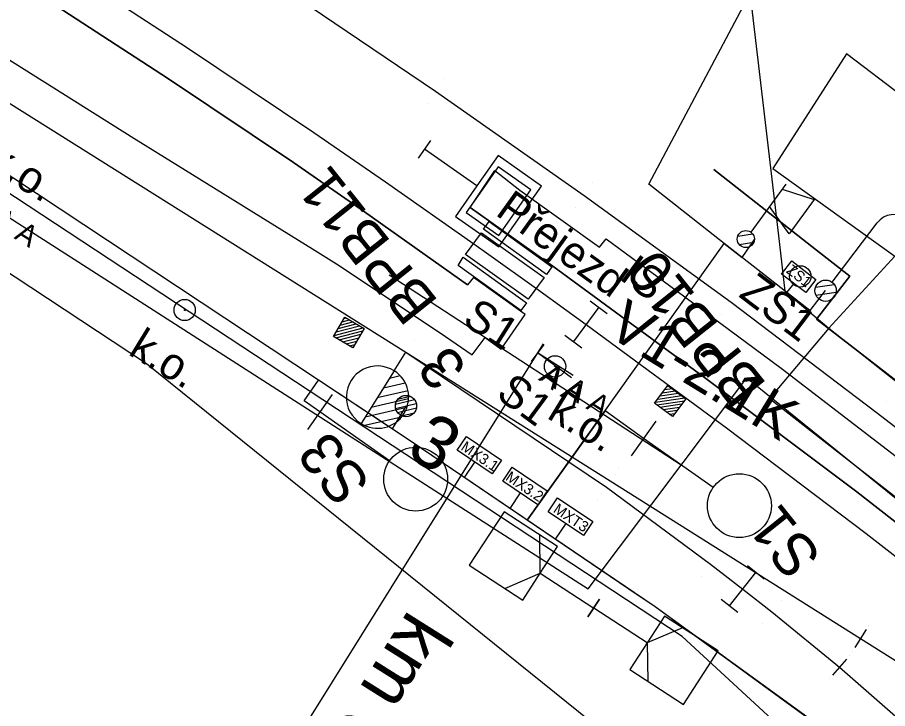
# Model space of a CAD drawing. Extents: x -620475 to -619963, y -1123010 to -1122510.
# Drawn here: x -620340.78 to -620299.89, y -1122684.84 to -1122652.35 of the extents above; entities that cross this region are included whole.
import ezdxf

# ---------------------------------------------------------------- set-up
doc = ezdxf.new("R2010")
doc.units = 0
for name, color, linetype in [('060601_EOV', 7, 'Continuous'), ('060604_ROZVODY_SEE', 7, 'Continuous'), ('HranDP', 7, 'Continuous'), ('Hranice parcel', 7, 'Continuous'), ('lomové body trasa', 7, 'Continuous'), ('PS 06-14-01_trasa_sdělovací_nové', 7, 'Continuous'), ('SEE', 7, 'Continuous'), ('SSZT', 7, 'Continuous'), ('UZEMNĚNÍ', 7, 'Continuous'), ('Vrstva 1', 7, 'Continuous'), ('Vrstva 12', 7, 'Continuous'), ('Vrstva 14', 7, 'Continuous'), ('Vrstva 16', 7, 'Continuous'), ('Vrstva 2', 7, 'Continuous'), ('Vrstva 25', 7, 'Continuous'), ('Vrstva 27', 7, 'Continuous'), ('Vrstva 3', 7, 'Continuous'), ('Vrstva 33', 7, 'Continuous'), ('Vrstva 4', 7, 'Continuous'), ('Vrstva 51', 7, 'Continuous'), ('Vrstva 6', 7, 'Continuous'), ('Vrstva 62', 7, 'Continuous'), ('Vrstva 7', 7, 'Continuous')]:
    doc.layers.add(name, color=color, linetype=linetype)

msp = doc.modelspace()

# ---------------------------------------------------------------- linework, layer by layer
at = {"layer": '060601_EOV'}
for p, q in [((-620319.299, -1122673.255), (-620319.788, -1122673.977)), ((-620317.154, -1122674.7), (-620317.648, -1122675.428)), ((-620315.01, -1122676.145), (-620315.508, -1122676.879))]:
    msp.add_line(p, q, dxfattribs=at)
msp.add_lwpolyline([(-620235.16, -1122712.242), (-620240.174, -1122718.342), (-620243.025, -1122715.998), (-620248.321, -1122722.765), (-620259.889, -1122713.575), (-620277.713, -1122700.902), (-620282.346, -1122705.302), (-620297.82, -1122689.49), (-620304.222, -1122684.862), (-620310.815, -1122680.061), (-620322.228, -1122672.322), (-620343.182, -1122658.459), (-620368.499, -1122642.897), (-620385.559, -1122631.811)], dxfattribs=at)
for points in [[(-620319.683, -1122672.048), (-620318.035, -1122673.159), (-620318.475, -1122673.81), (-620320.123, -1122672.7)], [(-620317.539, -1122673.493), (-620315.891, -1122674.603), (-620316.33, -1122675.255), (-620317.978, -1122674.145)], [(-620315.395, -1122674.938), (-620313.747, -1122676.048), (-620314.186, -1122676.7), (-620315.834, -1122675.59)]]:
    msp.add_lwpolyline(points, close=True, dxfattribs=at)
at = {"layer": '060604_ROZVODY_SEE'}
msp.add_line((-620304.307, -1122664.856), (-620304.643, -1122665.284), dxfattribs=at)
for points in [[(-620316.822, -1122675.988), (-620307.569, -1122662.984), (-620311.113, -1122660.198), (-620304.112, -1122646.984), (-620307.038, -1122645.433), (-620340.053, -1122630.257)], [(-620243.025, -1122715.998), (-620248.321, -1122722.765), (-620259.889, -1122713.575), (-620277.713, -1122700.902), (-620282.346, -1122705.302), (-620297.82, -1122689.49), (-620304.222, -1122684.862), (-620310.815, -1122680.061), (-620316.822, -1122675.988), (-620322.228, -1122672.322), (-620326.634, -1122669.408), (-620343.182, -1122658.459), (-620368.499, -1122642.897), (-620385.559, -1122631.811)], [(-620302.826, -1122665.182), (-620303.546, -1122666.133), (-620307.569, -1122662.984)]]:
    msp.add_lwpolyline(points, dxfattribs=at)
msp.add_lwpolyline([(-620304.396, -1122663.798), (-620303.263, -1122664.665), (-620303.741, -1122665.29), (-620304.874, -1122664.423)], close=True, dxfattribs=at)
at = {"layer": 'HranDP'}
msp.add_lwpolyline([(-620310.57, -1122708.76), (-620306.2, -1122698.65), (-620309.9, -1122688.62), (-620334.71, -1122668.63), (-620387.366, -1122633.877)], dxfattribs=at)
at = {"layer": 'Hranice parcel'}
for points in [[(-620310.57, -1122708.76), (-620306.2, -1122698.65), (-620309.9, -1122688.62), (-620334.71, -1122668.63), (-620387.366, -1122633.877)], [(-620302.66, -1122666.96), (-620267.81, -1122694.49), (-620266.86, -1122693.31), (-620261.82, -1122686.93), (-620261.22, -1122686.17), (-620299.15, -1122656.1), (-620301.83, -1122654.06), (-620305.28, -1122659.46), (-620299.56, -1122663.58), (-620302.66, -1122666.96)]]:
    msp.add_lwpolyline(points, dxfattribs=at)
at = {"layer": 'lomové body trasa'}
msp.add_lwpolyline([(-620316.822, -1122675.988), (-620307.569, -1122662.984), (-620306.73, -1122663.642), (-620306.11, -1122662.747)], dxfattribs=at)
at = {"layer": 'PS 06-14-01_trasa_sdělovací_nové'}
msp.add_lwpolyline([(-620248.321, -1122722.765), (-620259.889, -1122713.575), (-620277.711, -1122700.887), (-620282.346, -1122705.302), (-620297.82, -1122689.49), (-620310.815, -1122680.061), (-620322.228, -1122672.322), (-620343.182, -1122658.459), (-620368.499, -1122642.897), (-620385.559, -1122631.811)], dxfattribs=at)
at = {"layer": 'SEE'}
for points in [[(-620340.053, -1122630.257), (-620307.038, -1122645.433), (-620304.995, -1122662.882), (-620304.721, -1122665.223), (-620302.66, -1122666.96), (-620305.446, -1122670.265), (-620283.044, -1122687.742), (-620274.947, -1122694.711), (-620269.357, -1122688.084), (-620267.489, -1122689.555)], [(-620244.518, -1122694.296), (-620246.547, -1122692.66), (-620267.469, -1122718.6), (-620268.222, -1122719.534), (-620284.407, -1122704.62), (-620304.333, -1122686.26), (-620309.55, -1122681.453), (-620327.714, -1122669.483), (-620362.834, -1122646.339), (-620385.658, -1122631.923)]]:
    msp.add_lwpolyline(points, dxfattribs=at)
at = {"layer": 'SSZT'}
msp.add_line((-620309.595, -1122673.397), (-620323.304, -1122664.466), dxfattribs=at)
msp.add_lwpolyline([(-620386.367, -1122632.734), (-620363.271, -1122647.563), (-620313.966, -1122679.218), (-620306.51, -1122669.289), (-620273.137, -1122696.274), (-620258.422, -1122709.142), (-620248.072, -1122696.094)], dxfattribs=at)
at = {"layer": 'UZEMNĚNÍ'}
msp.add_line((-620304.307, -1122664.856), (-620304.643, -1122665.284), dxfattribs=at)
msp.add_lwpolyline([(-620302.826, -1122665.182), (-620303.546, -1122666.133), (-620307.569, -1122662.984), (-620311.113, -1122660.198), (-620304.112, -1122646.984), (-620307.038, -1122645.433), (-620340.053, -1122630.257)], dxfattribs=at)
at = {"layer": 'Vrstva 1'}
for p, q in [((-620323.174, -1122671.696), (-620326.634, -1122669.408)), ((-620322.521, -1122670.619), (-620323.174, -1122671.696)), ((-620313.165, -1122670.848), (-620316.822, -1122675.988)), ((-620311.36, -1122672.145), (-620313.165, -1122670.848))]:
    msp.add_line(p, q, dxfattribs=at)
for points in [[(-620375.899, -1122620.767), (-620371.626, -1122623.45), (-620362.665, -1122629.103), (-620357.095, -1122632.621), (-620348.688, -1122637.935), (-620341.5, -1122642.47), (-620339.854, -1122643.512), (-620333.156, -1122647.798), (-620327.653, -1122651.408), (-620321.139, -1122655.817), (-620314.146, -1122660.717), (-620307.245, -1122665.745), (-620300.366, -1122670.953), (-620293.063, -1122676.601)], [(-620379.075, -1122624.398), (-620379.008, -1122624.44), (-620374.378, -1122627.361), (-620367.833, -1122631.489), (-620360.993, -1122635.8), (-620354.976, -1122639.588), (-620353.476, -1122640.528), (-620346.441, -1122644.972), (-620339.555, -1122649.372), (-620332.789, -1122653.783), (-620326.854, -1122657.769), (-620323.491, -1122660.075), (-620319.328, -1122662.995), (-620318.623, -1122663.494), (-620316.382, -1122665.099), (-620314.967, -1122666.125), (-620314.061, -1122666.783), (-620307.461, -1122671.648), (-620300.906, -1122676.615), (-620294.546, -1122681.556)], [(-620379.075, -1122624.398), (-620379.008, -1122624.44), (-620374.378, -1122627.361), (-620367.833, -1122631.489), (-620360.993, -1122635.8), (-620354.976, -1122639.588), (-620353.476, -1122640.528), (-620346.441, -1122644.972), (-620339.555, -1122649.372), (-620332.789, -1122653.783), (-620326.854, -1122657.769), (-620323.491, -1122660.075), (-620319.328, -1122662.995), (-620318.623, -1122663.494), (-620316.382, -1122665.099), (-620314.967, -1122666.125), (-620314.061, -1122666.783), (-620307.461, -1122671.648), (-620300.906, -1122676.615), (-620294.546, -1122681.556)], [(-620383.649, -1122629.627), (-620378.269, -1122633.015), (-620362.958, -1122642.66), (-620347.616, -1122652.305), (-620342.456, -1122655.575), (-620322.526, -1122668.083), (-620312.925, -1122674.13), (-620301.163, -1122681.549), (-620292.126, -1122687.227), (-620282.992, -1122692.997), (-620276.394, -1122697.25), (-620266.758, -1122703.956), (-620255.894, -1122712.191)], [(-620326.634, -1122669.408), (-620343.182, -1122658.459), (-620368.499, -1122642.897), (-620385.559, -1122631.811)], [(-620322.526, -1122668.083), (-620313.097, -1122674.436), (-620308.214, -1122678.053), (-620306.7, -1122679.227), (-620305.337, -1122680.296), (-620302.152, -1122682.886), (-620294.636, -1122689.472), (-620288.443, -1122695.324), (-620284.812, -1122699.019), (-620282.778, -1122701.089), (-620280.313, -1122703.598), (-620275.628, -1122708.447), (-620262.902, -1122721.469), (-620255.487, -1122728.261), (-620248.439, -1122734.187)], [(-620326.567, -1122670.898), (-620327.304, -1122670.379), (-620326.634, -1122669.408)], [(-620316.822, -1122675.988), (-620322.228, -1122672.322), (-620323.174, -1122671.696)], [(-620288.271, -1122699.248), (-620297.82, -1122689.49), (-620304.222, -1122684.862), (-620310.815, -1122680.061), (-620311.612, -1122679.521), (-620316.822, -1122675.988)]]:
    msp.add_lwpolyline(points, dxfattribs=at)
at = {"layer": 'Vrstva 12'}
msp.add_lwpolyline([(-620293.461, -1122674.083), (-620303.242, -1122666.538), (-620301.662, -1122664.522), (-620303.242, -1122663.293), (-620308.054, -1122659.497), (-620303.242, -1122663.293), (-620301.662, -1122664.522), (-620303.242, -1122666.538), (-620293.461, -1122674.083)], dxfattribs=at)
at = {"layer": 'Vrstva 14'}
for points in [[(-620380.227, -1122625.715), (-620379.873, -1122625.938), (-620375.571, -1122628.636), (-620368.728, -1122632.945), (-620361.891, -1122637.249), (-620355.043, -1122641.547), (-620347.325, -1122646.469), (-620340.478, -1122650.803), (-620333.678, -1122655.247), (-620327.8, -1122659.174), (-620324.475, -1122661.491), (-620319.636, -1122664.917)], [(-620382.462, -1122628.27), (-620376.978, -1122631.728), (-620361.983, -1122641.198), (-620346.591, -1122650.915), (-620335.3, -1122658.037), (-620326.919, -1122663.23), (-620325.66, -1122664.016), (-620320.659, -1122667.355), (-620319.405, -1122668.214), (-620318.806, -1122667.396), (-620318.045, -1122667.942), (-620316.915, -1122666.32), (-620319.344, -1122664.58), (-620319.636, -1122664.917), (-620324.475, -1122661.491), (-620327.8, -1122659.174), (-620333.678, -1122655.247), (-620340.478, -1122650.803), (-620347.325, -1122646.469), (-620355.043, -1122641.547), (-620361.891, -1122637.249), (-620368.728, -1122632.945), (-620375.571, -1122628.636), (-620379.873, -1122625.938)]]:
    msp.add_lwpolyline(points, dxfattribs=at)
at = {"layer": 'Vrstva 16'}
msp.add_lwpolyline([(-620268.767, -1122698.19), (-620269.667, -1122699.332), (-620273.339, -1122696.067), (-620280.591, -1122690.258), (-620287.721, -1122684.651), (-620288.092, -1122685.04), (-620293.259, -1122680.96), (-620301.343, -1122674.65), (-620308.503, -1122669.28), (-620315.629, -1122664.052), (-620319.501, -1122661.293), (-620318.339, -1122659.55), (-620317.166, -1122660.468), (-620313.424, -1122663.148), (-620313.111, -1122662.768), (-620309.78, -1122665.216), (-620304.891, -1122668.836), (-620299.292, -1122673.151), (-620286.498, -1122683.168), (-620286.771, -1122683.508), (-620280.456, -1122688.482), (-620273.255, -1122694.212), (-620268.767, -1122698.19)], dxfattribs=at)
at = {"layer": 'Vrstva 2'}
for p, q in [((-620325.702, -1122666.98), (-620324.859, -1122666.762)), ((-620325.608, -1122666.82), (-620325.019, -1122666.667)), ((-620325.514, -1122666.66), (-620325.178, -1122666.573)), ((-620325.419, -1122666.5), (-620325.338, -1122666.479)), ((-620325.891, -1122667.3), (-620324.539, -1122666.95)), ((-620325.817, -1122667.416), (-620324.547, -1122667.088)), ((-620325.796, -1122667.139), (-620324.699, -1122666.856)), ((-620325.657, -1122667.51), (-620324.642, -1122667.248)), ((-620325.497, -1122667.604), (-620324.736, -1122667.408)), ((-620325.337, -1122667.699), (-620324.83, -1122667.568)), ((-620325.177, -1122667.793), (-620324.924, -1122667.727)), ((-620323.078, -1122668.963), (-620322.526, -1122668.083)), ((-620323.078, -1122668.963), (-620324.634, -1122671.442)), ((-620322.789, -1122669.204), (-620323.299, -1122669.32)), ((-620322.552, -1122669.54), (-620323.585, -1122669.776)), ((-620322.426, -1122669.9), (-620323.871, -1122670.23)), ((-620310.58, -1122670.142), (-620309.718, -1122670.015)), ((-620310.469, -1122669.993), (-620309.867, -1122669.904)), ((-620310.358, -1122669.844), (-620310.016, -1122669.793)), ((-620310.248, -1122669.695), (-620310.165, -1122669.683)), ((-620325.993, -1122670.08), (-620327.141, -1122671.717)), ((-620322.395, -1122670.283), (-620324.157, -1122670.686)), ((-620323.011, -1122670.531), (-620322.124, -1122670.319)), ((-620322.904, -1122670.3), (-620322.326, -1122670.161)), ((-620310.801, -1122670.44), (-620309.42, -1122670.236)), ((-620310.74, -1122670.563), (-620309.443, -1122670.372)), ((-620310.69, -1122670.29), (-620309.569, -1122670.126)), ((-620322.477, -1122670.692), (-620324.443, -1122671.141)), ((-620323.007, -1122670.736), (-620322.037, -1122670.503)), ((-620322.919, -1122670.921), (-620322.03, -1122670.707)), ((-620310.591, -1122670.674), (-620309.554, -1122670.521)), ((-620310.442, -1122670.785), (-620309.664, -1122670.67)), ((-620310.293, -1122670.895), (-620309.775, -1122670.819)), ((-620323.292, -1122673.194), (-620326.567, -1122670.898)), ((-620322.731, -1122671.14), (-620324.457, -1122671.534)), ((-620322.718, -1122671.078), (-620322.139, -1122670.939)), ((-620310.144, -1122671.006), (-620309.886, -1122670.968)), ((-620310.786, -1122671.326), (-620311.934, -1122672.964)), ((-620308.085, -1122674.441), (-620311.36, -1122672.145)), ((-620300.897, -1122681.126), (-620301.429, -1122681.972)), ((-620301.822, -1122682.51), (-620302.482, -1122683.262))]:
    msp.add_line(p, q, dxfattribs=at)
for points in [[(-620325.389, -1122666.449), (-620324.485, -1122666.982), (-620325.018, -1122667.887), (-620325.922, -1122667.354)], [(-620325.389, -1122666.449), (-620324.485, -1122666.982), (-620325.018, -1122667.887), (-620325.922, -1122667.354)], [(-620310.212, -1122669.647), (-620309.37, -1122670.274), (-620309.996, -1122671.116), (-620310.839, -1122670.49)], [(-620310.212, -1122669.647), (-620309.37, -1122670.274), (-620309.996, -1122671.116), (-620310.839, -1122670.49)]]:
    msp.add_lwpolyline(points, close=True, dxfattribs=at)
for points in [[(-620322.526, -1122668.083), (-620312.925, -1122674.13), (-620301.163, -1122681.549)], [(-620322.526, -1122668.083), (-620313.097, -1122674.436), (-620308.214, -1122678.053), (-620306.7, -1122679.227), (-620305.337, -1122680.296), (-620302.152, -1122682.886)]]:
    msp.add_lwpolyline(points, dxfattribs=at)
for centre, radius in [((-620322.521, -1122670.619), 0.5), ((-620322.064, -1122674.055), 1.5), ((-620306.856, -1122675.302), 1.5)]:
    msp.add_circle(centre, radius, dxfattribs=at)
for centre, start, end in [((-620323.861, -1122670.199), 57.653, 238.1225), ((-620323.857, -1122670.202), 237.9073, 57.8682)]:
    msp.add_arc(centre, 1.463, start, end, dxfattribs=at)
at = {"layer": 'Vrstva 25'}
for p, q in [((-620302.503, -1122664.801), (-620300.389, -1122662.012)), ((-620304.037, -1122664.496), (-620303.957, -1122664.556)), ((-620303.274, -1122665.028), (-620302.403, -1122664.908)), ((-620303.259, -1122665.404), (-620302.311, -1122665.273))]:
    msp.add_line(p, q, dxfattribs=at)
for centre in [(-620303.997, -1122664.526), (-620302.805, -1122665.2)]:
    msp.add_circle(centre, 0.5, dxfattribs=at)
msp.add_arc((-620299.592, -1122662.616), 1, 322.8473, 142.8473, dxfattribs=at)
at = {"layer": 'Vrstva 27'}
for p, q in [((-620332.962, -1122666.08), (-620332.876, -1122666.132)), ((-620315.56, -1122668.731), (-620315.474, -1122668.783))]:
    msp.add_line(p, q, dxfattribs=at)
for centre in [(-620332.919, -1122666.106), (-620315.517, -1122668.757)]:
    msp.add_circle(centre, 0.5, dxfattribs=at)
at = {"layer": 'Vrstva 3'}
for p, q in [((-620313.87, -1122665.681), (-620313.065, -1122666.275)), ((-620313.87, -1122665.681), (-620313.065, -1122666.275)), ((-620313.468, -1122665.978), (-620314.654, -1122667.588)), ((-620313.468, -1122665.978), (-620314.654, -1122667.588)), ((-620315.057, -1122667.291), (-620314.252, -1122667.885)), ((-620315.057, -1122667.291), (-620314.252, -1122667.885)), ((-620305.689, -1122678.749), (-620306.476, -1122678.132)), ((-620307.317, -1122680.014), (-620306.083, -1122678.44)), ((-620306.924, -1122680.322), (-620307.711, -1122679.705))]:
    msp.add_line(p, q, dxfattribs=at)
at = {"layer": 'Vrstva 33'}
for p, q in [((-620304.673, -1122660.188), (-620306.319, -1122662.447)), ((-620306.93, -1122662.634), (-620306.243, -1122662.526)), ((-620306.86, -1122663.028), (-620306.186, -1122662.922))]:
    msp.add_line(p, q, dxfattribs=at)
msp.add_lwpolyline([(-620304.85, -1122660.43), (-620303.343, -1122660.91), (-620304.521, -1122662.526), (-620305.439, -1122661.239)], dxfattribs=at)
msp.add_circle((-620306.555, -1122662.771), 0.401, dxfattribs=at)
at = {"layer": 'Vrstva 4'}
for points in [[(-620318.882, -1122662.306), (-620318.619, -1122661.946), (-620315.665, -1122664.074), (-620315.919, -1122664.443), (-620318.882, -1122662.306)], [(-620318.974, -1122662.471), (-620316.033, -1122664.574), (-620316.787, -1122665.599), (-620319.718, -1122663.504), (-620318.974, -1122662.471)], [(-620319.328, -1122662.995), (-620318.623, -1122663.494), (-620316.382, -1122665.099)], [(-620320.077, -1122664.008), (-620319.828, -1122663.627), (-620316.857, -1122665.763), (-620317.118, -1122666.125), (-620320.077, -1122664.008)]]:
    msp.add_lwpolyline(points, dxfattribs=at)
at = {"layer": 'Vrstva 51'}
msp.add_lwpolyline([(-620319.501, -1122661.293), (-620315.629, -1122664.052), (-620308.503, -1122669.28), (-620301.343, -1122674.65), (-620293.259, -1122680.96), (-620288.092, -1122685.04), (-620287.721, -1122684.651), (-620280.591, -1122690.258), (-620273.339, -1122696.067), (-620269.667, -1122699.332)], dxfattribs=at)
at = {"layer": 'Vrstva 6'}
for p, q in [((-620316.041, -1122667.724), (-620316.635, -1122668.528)), ((-620316.071, -1122667.703), (-620316.605, -1122668.549)), ((-620316.338, -1122668.126), (-620330.777, -1122691.249)), ((-620314.744, -1122669.301), (-620316.338, -1122668.126)), ((-620314.663, -1122669.182), (-620316.338, -1122668.126))]:
    msp.add_line(p, q, dxfattribs=at)
at = {"layer": 'Vrstva 62'}
for p, q in [((-620320.748, -1122655.238), (-620320.748, -1122655.238)), ((-620321.529, -1122656.396), (-620321.529, -1122656.396)), ((-620313.738, -1122660.134), (-620313.738, -1122660.134)), ((-620314.553, -1122661.3), (-620314.553, -1122661.3)), ((-620306.783, -1122665.199), (-620306.783, -1122665.199)), ((-620307.677, -1122666.314), (-620307.677, -1122666.314)), ((-620322.142, -1122667.49), (-620322.142, -1122667.49)), ((-620322.91, -1122668.677), (-620322.91, -1122668.677)), ((-620299.944, -1122670.391), (-620299.944, -1122670.391)), ((-620300.788, -1122671.515), (-620300.788, -1122671.515)), ((-620312.536, -1122673.534), (-620312.536, -1122673.534)), ((-620312.692, -1122673.835), (-620312.692, -1122673.835)), ((-620313.315, -1122674.727), (-620313.315, -1122674.727)), ((-620313.502, -1122675.037), (-620313.502, -1122675.037)), ((-620307.809, -1122677.461), (-620307.809, -1122677.461)), ((-620308.618, -1122678.645), (-620308.618, -1122678.645)), ((-620306.275, -1122678.641), (-620306.275, -1122678.641)), ((-620307.124, -1122679.813), (-620307.124, -1122679.813)), ((-620304.896, -1122679.744), (-620304.896, -1122679.744)), ((-620305.778, -1122680.848), (-620305.778, -1122680.848)), ((-620300.779, -1122680.954), (-620300.779, -1122680.954)), ((-620301.547, -1122682.144), (-620301.547, -1122682.144)), ((-620301.687, -1122682.347), (-620301.687, -1122682.347)), ((-620302.618, -1122683.425), (-620302.618, -1122683.425))]:
    msp.add_line(p, q, dxfattribs=at)
at = {"layer": 'Vrstva 7'}
for p, q in [((-620321.367, -1122658.144), (-620321.941, -1122658.962)), ((-620319.198, -1122660.276), (-620321.654, -1122658.553)), ((-620316.217, -1122678.48), (-620313.701, -1122680.114)), ((-620313.429, -1122679.695), (-620313.973, -1122680.533)), ((-620313.973, -1122680.533), (-620313.429, -1122679.695)), ((-620311.185, -1122681.748), (-620313.701, -1122680.114))]:
    msp.add_line(p, q, dxfattribs=at)
for points in [[(-620319.198, -1122660.276), (-620320.202, -1122661.707), (-620318.155, -1122663.142), (-620316.147, -1122660.28), (-620318.194, -1122658.845), (-620319.198, -1122660.276)], [(-620318.939, -1122660.457), (-620319.69, -1122661.528), (-620318.154, -1122662.605), (-620316.65, -1122660.46), (-620318.186, -1122659.383), (-620318.939, -1122660.457)], [(-620316.217, -1122678.48), (-620315.4, -1122677.222), (-620317.915, -1122675.587), (-620319.55, -1122678.103), (-620317.034, -1122679.737), (-620316.217, -1122678.48)], [(-620317.874, -1122679.192), (-620316.217, -1122678.48), (-620316.24, -1122676.676)], [(-620311.185, -1122681.748), (-620312.002, -1122683.006), (-620309.487, -1122684.641), (-620307.852, -1122682.125), (-620310.368, -1122680.491), (-620311.185, -1122681.748)], [(-620309.528, -1122681.036), (-620311.185, -1122681.748), (-620311.162, -1122683.552)]]:
    msp.add_lwpolyline(points, dxfattribs=at)

# ---------------------------------------------------------------- texts
at = {"layer": '060601_EOV'}
for s, p in [('MX3.1', (-620319.98, -1122672.649)), ('MX3.2', (-620317.879, -1122674.065)), ('MXT3', (-620315.637, -1122675.576))]:
    msp.add_text(s, height=0.5, rotation=326.029, dxfattribs=at).set_placement(p)
at = {"layer": '060604_ROZVODY_SEE'}
msp.add_text('ZS1', height=0.5, rotation=322.5799, dxfattribs=at).set_placement((-620304.691, -1122664.322))
at = {"layer": 'Vrstva 2'}
msp.add_text('3', height=2.5, rotation=327.8878, dxfattribs=at).set_placement((-620322.587, -1122672.896))
at = {"layer": 'Vrstva 25'}
msp.add_text('ZS1', height=1.5, rotation=322.8711, dxfattribs=at).set_placement((-620306.939, -1122665.446))
at = {"layer": 'Vrstva 27'}
for s, height, p in [('k.o.', 1.5, (-620342.294, -1122659.401)), ('V1-2.1K', 2, (-620313.166, -1122667.242)), ('k.o.', 1.5, (-620335.62, -1122668.17)), ('k.o.', 1.5, (-620315.951, -1122671.158))]:
    msp.add_text(s, height=height, rotation=328.4879, dxfattribs=at).set_placement(p)
at = {"layer": 'Vrstva 3'}
for s, height, rotation, p in [('BPB11', 2, 128.542, (-620320.953, -1122665.723)), ('BPB10', 2, 128.542, (-620305.526, -1122669.616)), ('IS', 1.5, 323.6053, (-620312.548, -1122664.624)), ('3', 2, 128.542, (-620319.589, -1122668.814)), ('S3', 2, 128.542, (-620324.117, -1122674.24)), ('S1', 2, 128.542, (-620302.932, -1122677.683))]:
    msp.add_text(s, height=height, rotation=rotation, dxfattribs=at).set_placement(p)
at = {"layer": 'Vrstva 4'}
msp.add_text('Přejezd', height=1.5, rotation=324.2373, dxfattribs=at).set_placement((-620318.371, -1122661.606))
at = {"layer": 'Vrstva 6'}
for s, height, rotation, p in [('  A A A A ', 1, 327.7824, (-620344.802, -1122660.307)), ('S1', 1.5, 327.7824, (-620319.93, -1122666.741)), ('  A A ', 1, 323.6053, (-620316.931, -1122668.931)), ('  A A A ', 1, 327.7824, (-620316.871, -1122668.972)), ('S1', 1.5, 323.6053, (-620318.352, -1122670.182)), ('km 63,371', 2.5, 237.7824, (-620322.376, -1122680.13))]:
    msp.add_text(s, height=height, rotation=rotation, dxfattribs=at).set_placement(p)

doc.saveas('drawing.dxf')
